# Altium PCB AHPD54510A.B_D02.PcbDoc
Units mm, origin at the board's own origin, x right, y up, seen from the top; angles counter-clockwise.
Board outline 70.4 x 70.4 mm, 2 copper layers (Top Layer, Bottom Layer), stack 1.57 mm thick; 18 components, 11 nets, 73 pads, 315 vias.
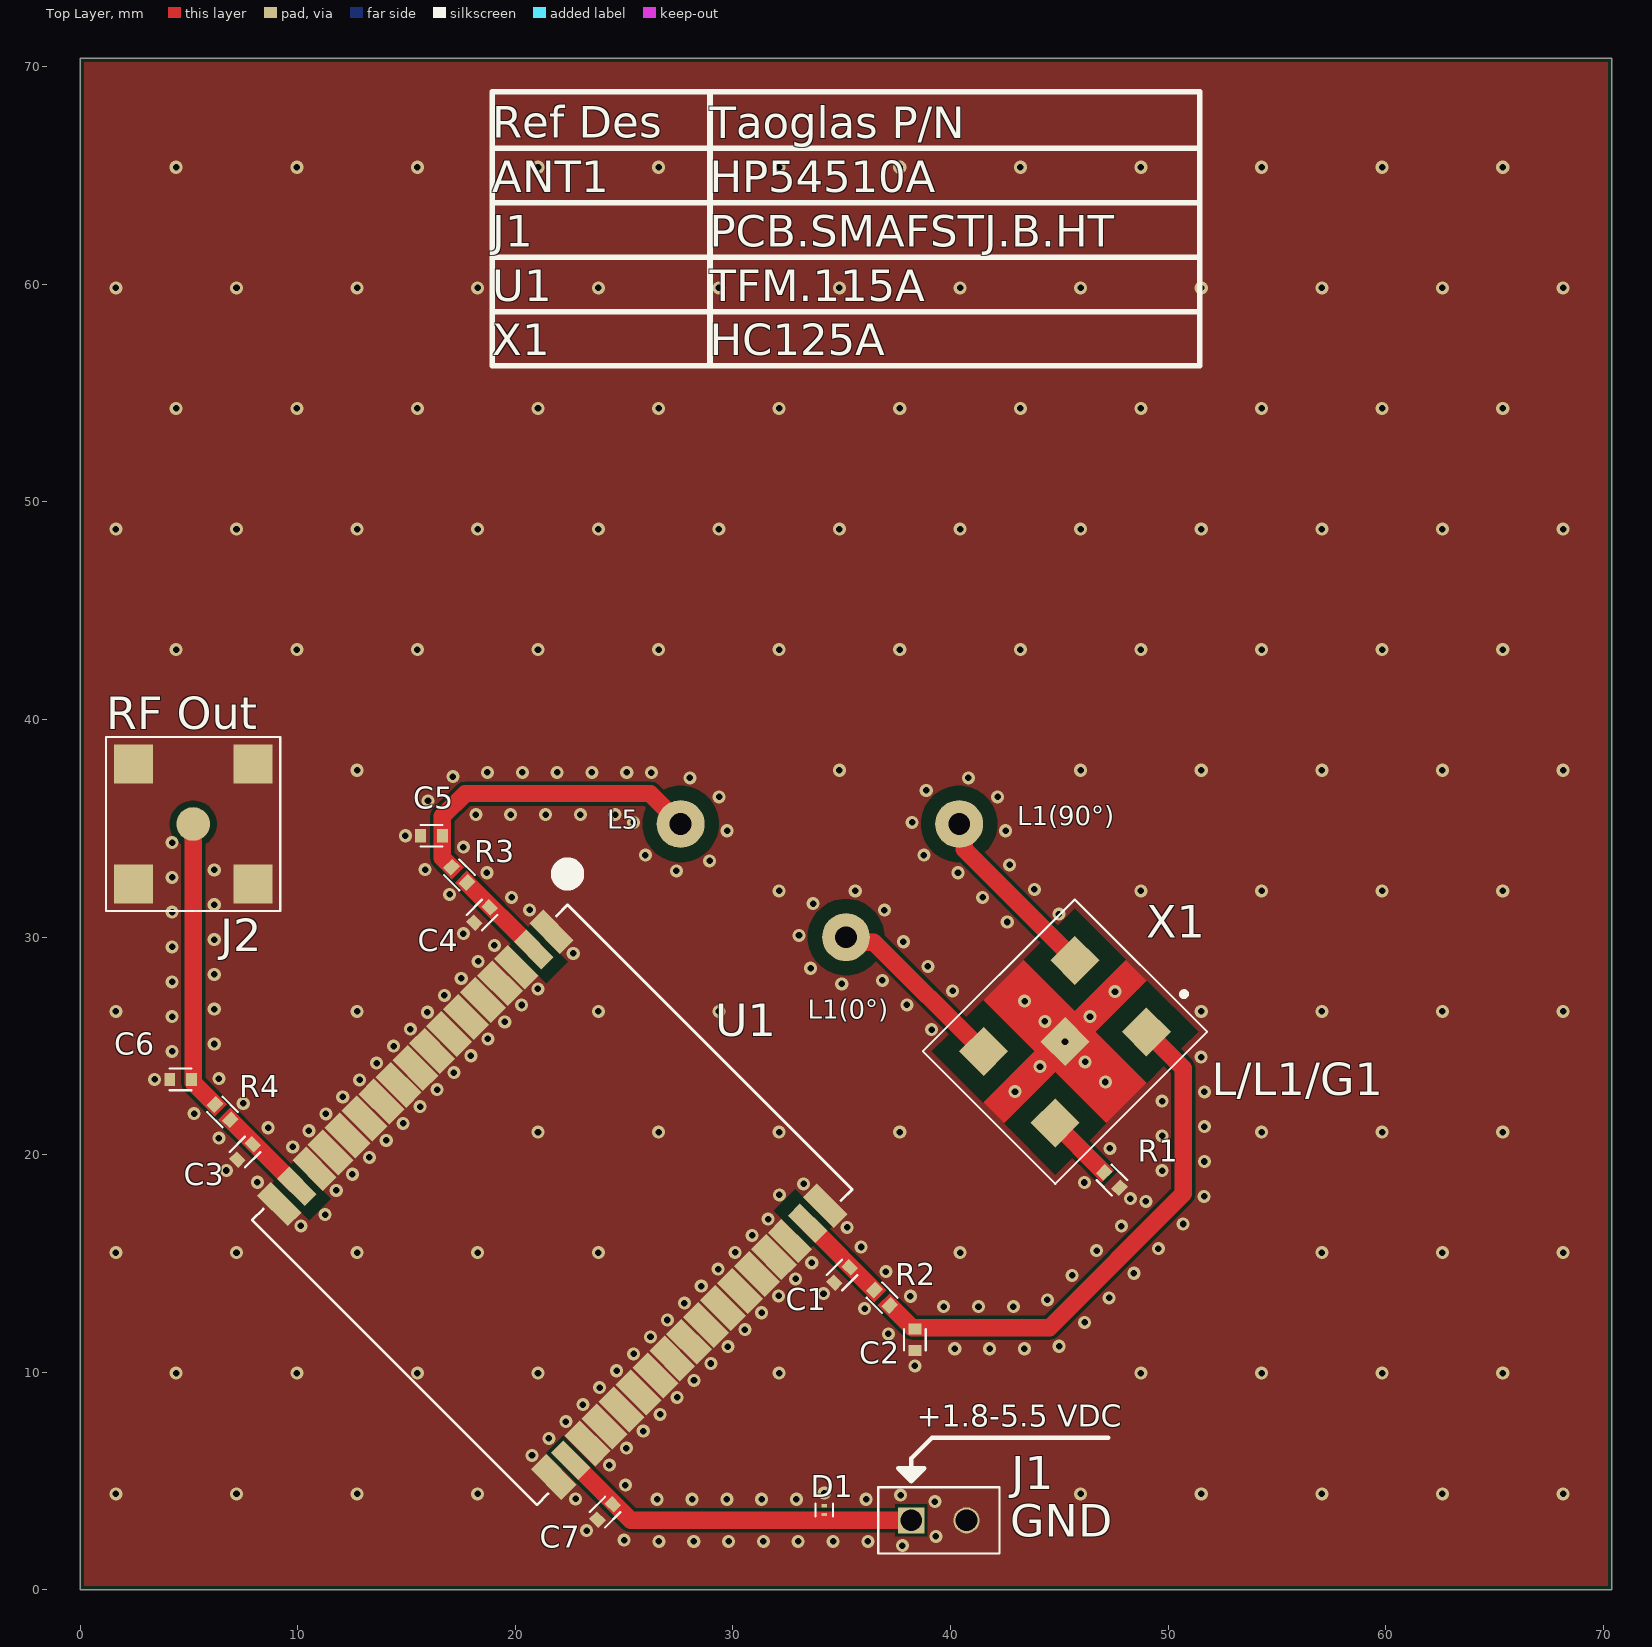
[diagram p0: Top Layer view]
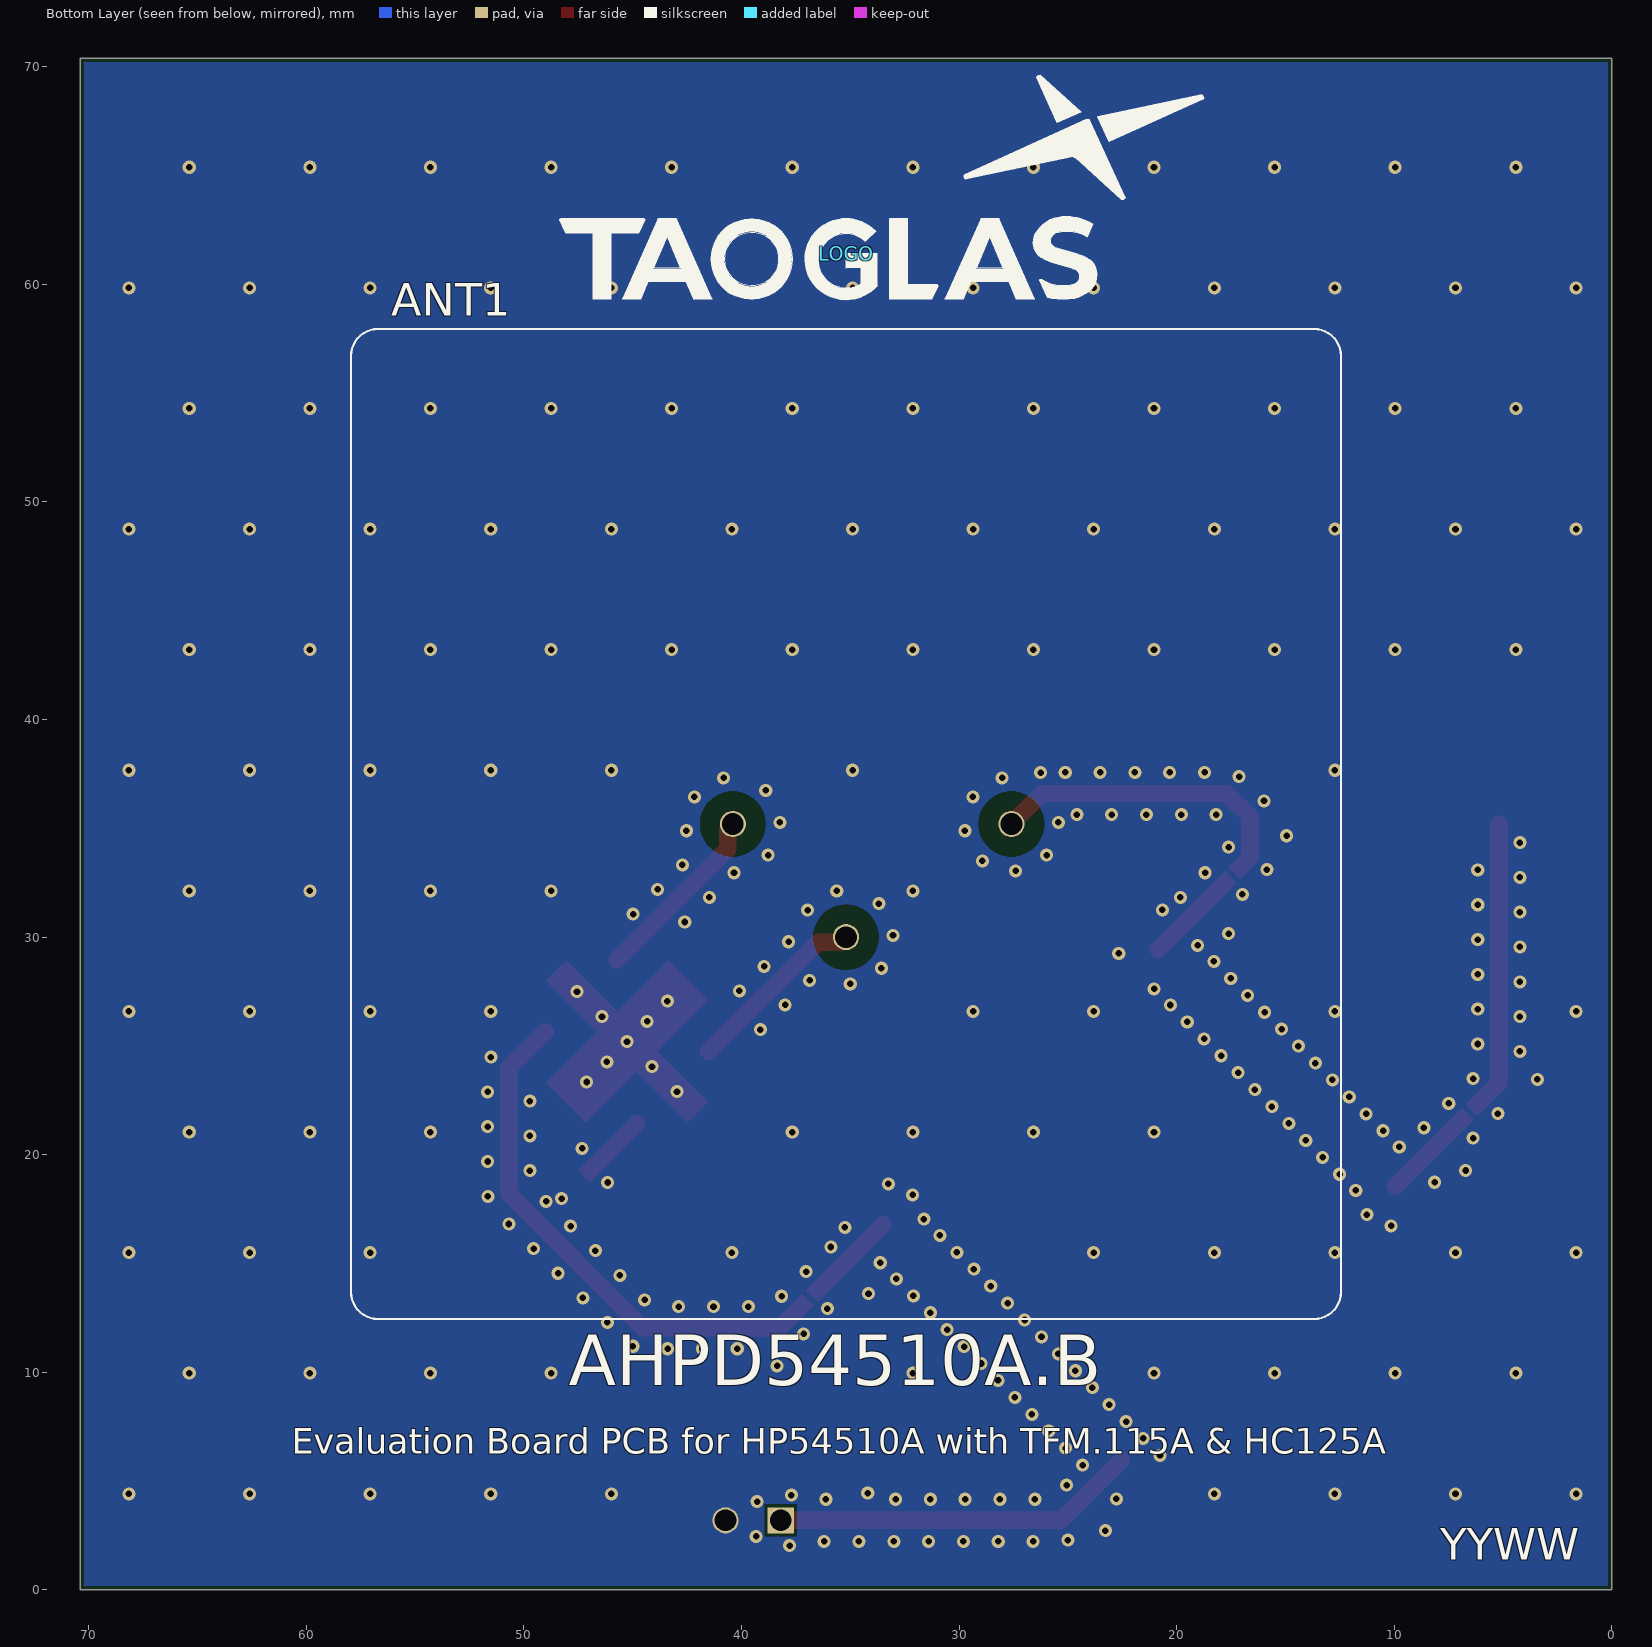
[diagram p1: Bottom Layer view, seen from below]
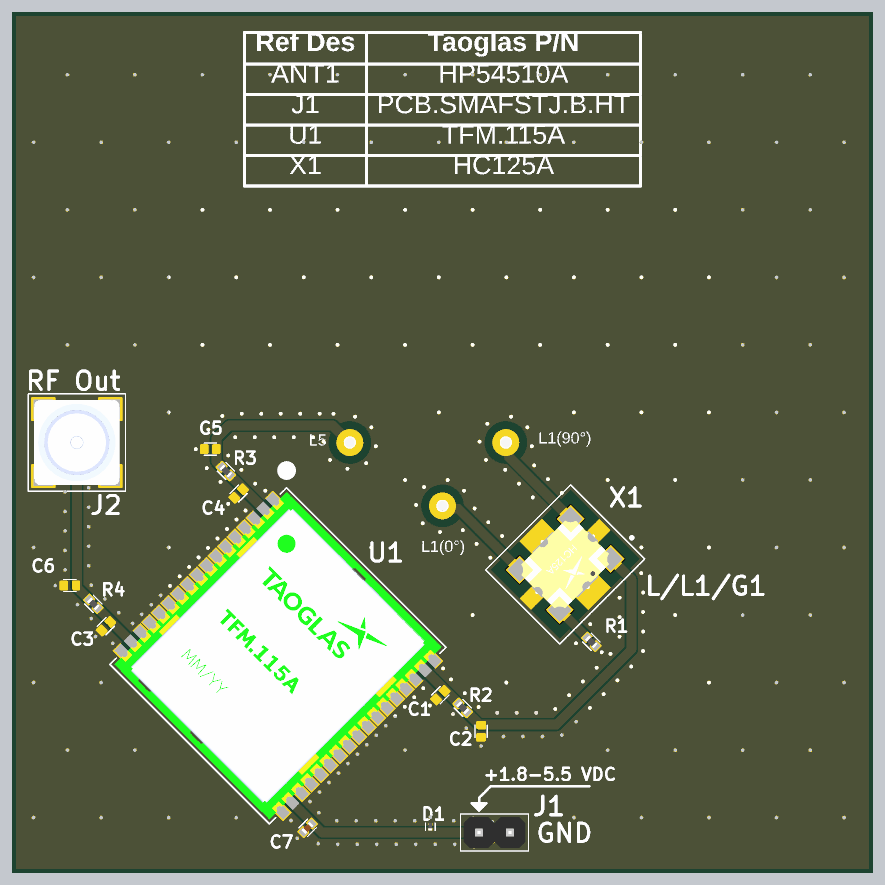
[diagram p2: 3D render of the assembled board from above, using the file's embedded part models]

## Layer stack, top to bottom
Top Solder Mask: solder mask 0.01, Solder Resist, Dk 3.5
Top Layer: signal copper 0.035
Dielectric: core 1.5, FR-4, Dk 4.2
Bottom Layer: signal copper 0.035
Bottom Solder Mask: solder mask 0.01, Solder Resist, Dk 3.5

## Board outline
0,0 70.4,0 70.4,70.4 0,70.4

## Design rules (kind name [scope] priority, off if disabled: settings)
BoardOutlineClearance [All] p1: gap=0.196 ignorepadtopadclearanceinfootprint=FALSE
Clearance Clearance_Polygon [All] p1: gap=0.14 ignorepadtopadclearanceinfootprint=FALSE except(0.05: Arc-Arc Arc-Track Track-Track; 0.1: Arc-SMDPad Arc-THPad Track-SMDPad Track-THPad SMDPad-SMDPad SMDPad-THPad THPad-THPad; 0.2: Arc-Via Arc-Text Arc-Hole Track-Via Track-Text Track-Hole SMDPad-Via SMDPad-Text SMDPad-Hole THPad-Via THPad-Text THPad-Hole Via-Via Via-Text Via-Hole Fill-Text Fill-Hole Poly-Text Poly-Hole Region-Text Region-Hole Text-Text Text-Hole)
HoleSize [All] p1: absolutevalues=TRUE maxlimit=6 minlimit=0.15 maxpercent=80.000 minpercent=20.000
MinimumAnnularRing [All] p1: minimumring=0.1
MinimumSolderMaskSliver [All vs InPadClass('All Pads')] p1: minsoldermaskwidth=0.05
PolygonConnect [All] p1: connectstyle=Direct reliefconductorwidth=0.254 reliefentries=4 polygonreliefangle="90 Angle" airgapwidth=0.254
RoutingVias [All] p1: holewidth=0.3 width=0.8 viastyle="Through Hole" minholewidth=0.15 minwidth=0.65 maxholewidth=6 maxwidth=6.5
SilkToSilkClearance [All] p1: silktosilkclearance=0.1
SilkToSolderMaskClearance [IsPad or IsVia vs OnLayer('Top Overlay')] p1: minsilkscreentomaskgap=0.05 clearancetoexposedcopper=FALSE
SilkToSolderMaskClearance SilkToSolderMaskClearance_1 [IsPad or IsVia vs OnLayer('Bottom Overlay')] p2: minsilkscreentomaskgap=0.05 clearancetoexposedcopper=FALSE
SolderMaskExpansion [Not IsVia] p1: expansion=0.1 istentingtop=FALSE
SupplyNets "Schematic Supply Nets" [InNet('GND')] p1: voltage=0.000
Width [All] p1: maxlimit=5 minlimit=0.1 preferedwidth=1 minimp=50.000000 maximp=50.000000 favimp=50.000000
26 further rules are at their usual default settings.

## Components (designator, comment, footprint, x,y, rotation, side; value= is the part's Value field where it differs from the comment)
ANT1 "TAOGLAS_HP54510A" TAOGLAS_HP54510A 35.2,35.2 r180 bottom
C1 "DNF" "0402 - DNF" 35.019,14.473 r225 top
C2 "DNF" "0402 - DNF" 38.368,11.499 r90 top
C3 "DNF" "0402 - DNF" 7.583,20.13 r45 top
C4 "DNF" "0402 - DNF" 18.473,31.019 r45 top
C5 "DNF" "0402 - DNF" 16.15,34.66 r180 top
C6 "DNF" "0402 - DNF" 4.623,23.467 r180 top
C7 "100pF" "Capacitor - 0402 - GRM" 24.13,3.583 r45 top
D1 "ESD245B1W0201E6327XTSA1" "Diode - 0201 (0603 Metric) - DSN0603-2" 34.2,3.67 r90 top
J1 "PREC002SAAN-RC" SULLINS_PREC002SAAN-RC 39.47,3.2 r0 top
J2 "TAOGLAS_PCB.SMAFSTJ.B.HT" TAOGLAS_PCB.SMAFSTJ.B.HT 5.2,35.2 r90 top
LOGO "TAOGLAS_LOGO" "TAOGLAS_LOGO - No R - 10.3mm" 35.2,61.4 r180 bottom
R1 "49.9" "Resistor - 0402 - ERJ-2RK" 47.415,18.837 r315 top
R2 "0" "Resistor - 0402 - RC_L" 36.861,13.428 r315 top
R3 "0" "Resistor - 0402 - RC_L" 17.428,32.861 r135 top
R4 "0" "Resistor - 0402 - RC_L" 6.552,21.959 r135 top
U1 "TAOGLAS_TFM.115A" TAOGLAS_TFM.115A 21.7,17.7 r315 top
X1 "TAOGLAS_HC125A" TAOGLAS_HC125A 45.264,25.2 r225 top

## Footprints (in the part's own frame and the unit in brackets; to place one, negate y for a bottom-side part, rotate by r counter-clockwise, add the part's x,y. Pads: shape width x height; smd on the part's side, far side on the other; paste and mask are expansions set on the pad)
"0402 - DNF" [mm]
  rect 0.5x0.6 smd paste-2539.97 mask+0.1: 1(-0.5,0) 2(0.5,0)
  silkscreen extent -0.5,-0.5 0.5,0.5
"Capacitor - 0402 - GRM" [mm]
  rect 0.5x0.6 smd mask+0.1: 1(-0.5,0) 2(0.5,0)
  silkscreen extent -0.5,-0.5 0.5,0.5, body extent -0.5,-0.25 0.5,0.25, height 0.55
"Diode - 0201 (0603 Metric) - DSN0603-2" [mm]
  rect 0.14x0.24 smd paste-2539.97 mask+0.05: 1(-0.2,0) 2(0.2,0)
  silkscreen extent -0.3,-0.4 0.3,0.4, body extent -0.3,-0.15 0.3,0.15, height 0.32
"Resistor - 0402 - ERJ-2RK" [mm]
  rect 0.5x0.6 smd mask+0.1: 1(-0.5,0) 2(0.5,0)
  silkscreen extent -0.5,-0.5 0.5,0.5, body extent -0.5,-0.25 0.5,0.25, height 0.35
"Resistor - 0402 - RC_L" [mm]
  rect 0.5x0.6 smd mask+0.1: 1(-0.5,0) 2(0.5,0)
  silkscreen extent -0.5,-0.5 0.5,0.5, body extent -0.5,-0.25 0.5,0.25, height 0.4
SULLINS_PREC002SAAN-RC [mm] "2 Positions Header, 0.100\" (2.54mm)"
  rect 1.2x1.2 hole 1 mask+0.1: 1(-1.27,0)
  round 1.2 hole 1 mask+0.1: 2(1.27,0)
  silkscreen extent -2.79,-1.52 2.79,2.12, body extent -2.54,-1.27 2.54,1.27, height 8.38
TAOGLAS_HC125A [mm] "Low Profile, High Performance Multiband GNSS Hybrid Coupler"
  rect 1.6x1.6 smd paste-0.1 mask+0.1: 1(-2.96,2.325) 2(2.96,2.325) 3(2.96,-2.325) 4(-2.96,-2.325)
  rect 1.6x1.6 smd: 5(0,0)
  Top Layer region: -4.62,0.665 -4.62,-0.665 -1.3,-0.665 -1.3,-3.985 1.3,-3.985 1.3,-0.665 4.62,-0.665 4.62,0.665 1.3,0.665 1.3,3.985 -1.3,3.985 -1.3,0.665
  silkscreen extent -5.51,-4.3 4.94,4.3, body extent -3.17,-2.54 3.18,2.54, height 1.5
TAOGLAS_HP54510A [mm] "Passive Multiband High Precision GNSS L1/L5 Stacked Patch Antenna"
  round 1.2 / inner round 2.2 / far side round 2.2 hole 1 paste-2539.97: 1(0,-5.2) 2(-5.2,0) 3(7.6,0)
  Bottom Layer pour cut-out: 7.6,-1.747 8.27,-1.614 8.837,-1.235 9.217,-0.667 9.35,0.003 9.35,0.003 9.35,0.003 9.217,0.672 8.837,1.24 8.27,1.619 7.6,1.753 7.6,1.753 6.93,1.619 6.363,1.24 5.983,0.672 5.85,0.003 5.85,0.003 5.85,0.003 5.983,-0.667 6.363,-1.235 6.93,-1.614 7.6,-1.747
  Bottom Layer pour cut-out: -5.2,-1.747 -4.53,-1.614 -3.963,-1.235 -3.583,-0.667 -3.45,0.003 -3.45,0.003 -3.45,0.003 -3.583,0.672 -3.963,1.24 -4.53,1.619 -5.2,1.753 -5.2,1.753 -5.87,1.619 -6.437,1.24 -6.817,0.672 -6.95,0.003 -6.95,0.003 -6.95,0.003 -6.817,-0.667 -6.437,-1.235 -5.87,-1.614 -5.2,-1.747
  Bottom Layer pour cut-out: 0,-6.947 0.67,-6.814 1.237,-6.435 1.617,-5.867 1.75,-5.197 1.75,-5.197 1.75,-5.197 1.617,-4.528 1.237,-3.96 0.67,-3.581 0,-3.447 0,-3.447 -0.67,-3.581 -1.237,-3.96 -1.617,-4.528 -1.75,-5.197 -1.75,-5.197 -1.75,-5.197 -1.617,-5.867 -1.237,-6.435 -0.67,-6.814 0,-6.947
  Multi-Layer pour cut-out: 6.1,0 6.214,-0.574 6.539,-1.061 7.026,-1.386 7.6,-1.5 7.6,-1.5 8.174,-1.386 8.661,-1.061 8.986,-0.574 9.1,0 9.1,0 8.986,0.574 8.661,1.061 8.174,1.386 7.6,1.5 7.6,1.5 7.026,1.386 6.539,1.061 6.214,0.574 6.1,0
  Multi-Layer pour cut-out: -6.7,0 -6.586,-0.574 -6.261,-1.061 -5.774,-1.386 -5.2,-1.5 -5.2,-1.5 -4.626,-1.386 -4.139,-1.061 -3.814,-0.574 -3.7,0 -3.7,0 -3.814,0.574 -4.139,1.061 -4.626,1.386 -5.2,1.5 -5.2,1.5 -5.774,1.386 -6.261,1.061 -6.586,0.574 -6.7,0
  Multi-Layer pour cut-out: -1.5,-5.2 -1.386,-5.774 -1.061,-6.261 -0.574,-6.586 0,-6.7 0,-6.7 0.574,-6.586 1.061,-6.261 1.386,-5.774 1.5,-5.2 1.5,-5.2 1.386,-4.626 1.061,-4.139 0.574,-3.814 0,-3.7 0,-3.7 -0.574,-3.814 -1.061,-4.139 -1.386,-4.626 -1.5,-5.2
  silkscreen extent -22.75,-22.75 22.75,22.75, body extent -22.5,-22.5 22.5,22.5, height 10.2
"TAOGLAS_LOGO - No R - 10.3mm" [mm] "Total Height from bottom of the text to the top of the star is 10.3mm"
  silkscreen extent -13.15,-2.12 16.43,8.2
TAOGLAS_PCB.SMAFSTJ.B.HT [mm] "SMA (F) Surface Mount PCB Jack"
  round 1.55 smd paste-0.1 mask+0.1: 1(0,0)
  rect 1.8x1.8 smd paste-0.1 mask+0.1: 2(-2.75,2.75) 3(2.75,2.75) 4(-2.75,-2.75) 5(2.75,-2.75)
  silkscreen extent -4,-4 4,4, body extent -3.5,-3.5 3.5,3.5, height 10.23
TAOGLAS_TFM.115A [mm] "GNSS Front End Module for Bands L1, B1, G1, L Band and L5"
  rect 2x0.9 smd paste-2539.97 mask+0: 1(-8.9,8.85) 3(-8.9,6.55) 15(-8.9,-6.55) 17(-8.9,-8.85) 32(8.9,6.55) 34(8.9,8.85)
  rect 1.8x0.8 smd paste-2539.97: 2(-8.9,7.7) 16(-8.9,-7.7) 19(8.9,-7.7) 33(8.9,7.7)
  rect 2x1 smd paste-2539.97 mask+0: 4(-8.9,5.5) 5(-8.9,4.4) 6(-8.9,3.3) 7(-8.9,2.2) 8(-8.9,1.1) 9(-8.9,0) 10(-8.9,-1.1) 11(-8.9,-2.2) 12(-8.9,-3.3) 13(-8.9,-4.4) 14(-8.9,-5.5) 18(8.9,-8.8) 20(8.9,-6.6) 21(8.9,-5.5) 22(8.9,-4.4) 23(8.9,-3.3) 24(8.9,-2.2) 25(8.9,-1.1) 26(8.9,0) 27(8.9,1.1) 28(8.9,2.2) 29(8.9,3.3) 30(8.9,4.4) 31(8.9,5.5)
  silkscreen extent -10.5,-10.25 9.25,11.5, body extent -9,-10 9,10, height 2.74

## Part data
ANT1: library part CMP-270-000002-3, "Passive Multiband High Precision GNSS L1/L5 Stacked Patch Antenna", Temp_High=+85C, Temp_Low=-40C
C1 C2 C3 C4 C5 C6: library part CMP-00006-25, "Do Not Fit"
C7: library part CMP-001-00343-45, "100 pF ±5% 50V Ceramic Capacitor C0G, NP0 0402 (1005 Metric)", Max. Operating Temperature=125°C, Min. Operating Temperature=-55°C, Package / Case="0402 (1005 Metric)", Temperature Coefficient="C0G, NP0", Tolerance=±5%, Voltage - Rated=50V
D1: library part CMP-004-00167-10, "7.5V Clamp 5.5A (8/20µs) Ipp Tvs Diode Surface Mount WLL-2-3", Capacitance @ Frequency="5.8pF @ 1GHz", Current - Peak Pulse (10/1000µs)="5.5A (8/20µs)", Max. Operating Temperature=125°C, Max. Voltage - Clamping @ Ipp=7.5V, Min. Operating Temperature=-55°C, Package / Case="0201 (0603 Metric)", Power - Peak Pulse=44W, Power Line Protection=No, Supplier Device Package=WLL-2-3, Voltage - Reverse Standoff (Typ)=5.5V
J1: library part CMP-002-00180-7, "Connector Header Through Hole 2 position 0.100\" (2.54mm)", Temp_High=105°C, Temp_Low=-40°C
J2: library part CMP-028-000009-10, "SMA (F) Surface Mount PCB Jack", Temp_High=+85C, Temp_Low=-40C
LOGO: library part CMP-048-000000-2, "Silkscreen Logo - Standard"
R1: library part CMP-009-00256-10, "49.9 Ohms ±1% 0.1W, 1/10W Chip Resistor 0402 (1005 Metric) Automotive AEC-Q200 Thick Film", Max. Operating Temperature=155°C, Min. Operating Temperature=-25°C, Package / Case="0402 (1005 Metric)", Power (Watts)=100mW, Temperature Coefficient=±100ppm/°C, Tolerance=±1%
R2 R3 R4: library part CMP-009-00375-4, "0 Ohms Jumper Chip Resistor 0402 (1005 Metric) Moisture Resistant Thick Film", Max. Operating Temperature=155°C, Min. Operating Temperature=-55°C, Package / Case="0402 (1005 Metric)"
U1: library part CMP-559-000000-3, "Surface mount GNSS front-end module covering L1+B1+G1/L5+L-band", Temp_High=+85C, Temp_Low=-40C
X1: library part CMP-002-000151-19, "Low Profile, High Performance Multiband GNSS Hybrid Coupler", Center Frequency=1.39GHz

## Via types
v1: diameter 0.6, hole 0.3, Top Layer to Bottom Layer, tented both sides, 315 vias

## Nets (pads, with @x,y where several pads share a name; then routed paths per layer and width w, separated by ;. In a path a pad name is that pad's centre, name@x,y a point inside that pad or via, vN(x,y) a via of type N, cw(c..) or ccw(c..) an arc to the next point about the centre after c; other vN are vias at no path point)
GND: C1.2 C2.1 C3.1 C4.1 C5.2 C6.2 C7.1 D1.2 J1.2 J2.2 J2.3 J2.4 J2.5 R1.2 U1.1 U1.3 U1.4 U1.5 U1.6 U1.7 U1.8 U1.9 U1.10 U1.11 U1.12 U1.13 U1.14 U1.15 U1.17 U1.18 U1.20 U1.21 U1.22 U1.23 U1.24 U1.25 U1.26 U1.27 U1.28 U1.29 U1.30 U1.31 U1.32 U1.34 X1.5
  other v1: 37.792,2.039 26.603,2.231 28.203,2.231 29.803,2.231 31.403,2.231 33.003,2.231 34.603,2.231 36.203,2.231 25.004,2.29 39.334,2.465 23.276,2.73 39.285,4.065 22.771,4.184 26.524,4.169 28.124,4.169 29.724,4.169 31.324,4.169 32.924,4.169 36.124,4.169 37.712,4.361 1.648,4.419 7.19,4.419 12.732,4.419 18.274,4.419 45.984,4.419 51.526,4.419 57.068,4.419 62.61,4.419 68.152,4.419 34.2,4.455 25.062,4.819 24.326,5.74 20.771,6.184 25.104,6.518 21.549,6.962 25.882,7.295 22.326,7.74 26.66,8.073 23.104,8.518 27.438,8.851 23.882,9.295 28.215,9.629 4.419,9.961 9.961,9.961 15.503,9.961 21.045,9.961 32.129,9.961 48.755,9.961 54.297,9.961 59.839,9.961 65.381,9.961 24.66,10.073 38.368,10.299 28.993,10.407 25.438,10.851 40.198,11.084 41.798,11.084 43.398,11.084 29.771,11.185 44.994,11.199 26.215,11.629 37.152,11.768 30.549,11.962 46.162,12.292 26.993,12.407 31.327,12.74 36.055,12.933 39.689,13.021 41.289,13.021 42.889,13.021 27.771,13.185 44.459,13.329 47.294,13.424 38.162,13.498 32.105,13.518 34.166,13.619 28.549,13.962 32.882,14.296 45.59,14.46 48.425,14.555 37.03,14.629 29.327,14.74 33.625,15.038 1.648,15.503 7.19,15.503 12.732,15.503 18.274,15.503 23.816,15.503 30.105,15.518 40.442,15.503 57.068,15.503 62.61,15.503 68.152,15.503 46.722,15.592 49.556,15.686 35.899,15.76 30.882,16.296 35.251,16.665 10.149,16.735 47.853,16.723 50.688,16.818 31.625,17.038 11.262,17.249 48.985,17.854 48.269,17.984 51.658,18.09 32.138,18.151 11.775,18.362 33.251,18.665 8.149,18.735 46.158,18.725 12.518,19.104 6.73,19.276 49.731,19.269 51.669,19.69 13.295,19.882 47.329,20.294 9.775,20.362 14.073,20.66 6.378,20.763 49.731,20.869 21.045,21.045 26.587,21.045 32.129,21.045 37.671,21.045 54.297,21.045 59.839,21.045 65.381,21.045 10.518,21.104 8.64,21.241 51.669,21.29 14.851,21.438 5.246,21.894 11.295,21.882 15.629,22.215 7.5,22.363 49.731,22.469 12.073,22.66 42.966,22.902 51.669,22.89 16.407,22.993 47.121,23.344 12.851,23.438 3.423,23.467 6.377,23.503 17.185,23.771 44.115,24.051 13.629,24.215 46.192,24.272 51.516,24.483 17.962,24.549 4.231,24.748 14.407,24.993 6.169,25.09 45.264,25.2 18.74,25.327 39.131,25.752 15.185,25.771 19.518,26.105 44.336,26.128 4.231,26.348 46.413,26.349 15.962,26.549 1.648,26.587 12.732,26.587 23.816,26.587 29.358,26.587 51.526,26.587 57.068,26.587 62.61,26.587 68.152,26.587 6.169,26.69 20.296,26.882 38,26.883 43.408,27.056 16.74,27.327 47.562,27.498 40.095,27.527 21.038,27.625 35.004,27.848 4.231,27.948 36.869,28.014 17.518,28.105 6.169,28.29 33.576,28.57 38.964,28.659 18.296,28.882 22.665,29.251 4.231,29.548 19.038,29.625 37.833,29.79 6.169,29.89 33.041,30.078 17.619,30.166 42.61,30.696 44.986,31.06 4.231,31.148 20.665,31.251 36.965,31.247 6.169,31.49 33.687,31.541 19.832,31.828 41.479,31.827 16.986,31.969 32.129,32.129 35.625,32.122 48.755,32.129 54.297,32.129 59.839,32.129 65.381,32.129 43.855,32.191 4.231,32.748 18.7,32.959 40.347,32.959 27.404,33.048 6.169,33.09 15.855,33.1 42.723,33.322 28.937,33.505 25.976,33.77 38.776,33.77 17.619,34.138 4.231,34.348 14.95,34.66 29.737,34.89 42.537,34.89 25.441,35.278 38.241,35.278 18.192,35.631 19.792,35.631 21.392,35.631 22.992,35.631 24.592,35.631 15.991,36.261 29.365,36.447 42.165,36.447 38.887,36.741 28.025,37.322 40.825,37.322 17.135,37.378 18.724,37.569 20.324,37.569 21.924,37.569 23.524,37.569 25.124,37.569 26.254,37.558 12.732,37.671 34.9,37.671 45.984,37.671 51.526,37.671 57.068,37.671 62.61,37.671 68.152,37.671 4.419,43.213 9.961,43.213 15.503,43.213 21.045,43.213 26.587,43.213 32.129,43.213 37.671,43.213 43.213,43.213 48.755,43.213 54.297,43.213 59.839,43.213 65.381,43.213 1.648,48.755 7.19,48.755 12.732,48.755 18.274,48.755 23.816,48.755 29.358,48.755 34.9,48.755 40.442,48.755 45.984,48.755 51.526,48.755 57.068,48.755 62.61,48.755 68.152,48.755 4.419,54.297 9.961,54.297 15.503,54.297 21.045,54.297 26.587,54.297 32.129,54.297 37.671,54.297 43.213,54.297 48.755,54.297 54.297,54.297 59.839,54.297 65.381,54.297 1.648,59.839 7.19,59.839 12.732,59.839 18.274,59.839 23.816,59.839 29.358,59.839 34.9,59.839 40.442,59.839 45.984,59.839 51.526,59.839 57.068,59.839 62.61,59.839 68.152,59.839 4.419,65.381 9.961,65.381 15.503,65.381 21.045,65.381 26.587,65.381 32.129,65.381 37.671,65.381 43.213,65.381 48.755,65.381 54.297,65.381 59.839,65.381 65.381,65.381
NetANT1_1: ANT1.1 X1.3 | length 8.5
  Top Layer w0.8: ANT1.1 35.43,29.77 36.482,29.77 X1.3@41.502,24.751
NetANT1_2: ANT1.2 X1.4 | length 8.4
  Top Layer w0.8: ANT1.2 40.63,34.97 40.63,34.046 X1.4@45.713,28.963
NetANT1_3: ANT1.3 C5.1 R3.2 | length 14.6
  Top Layer w0.8: R3.2 16.65,33.639 16.65,34.731 C5.1 16.65,35.55 17.7,36.6 26.2,36.6 ANT1.3
NetC1_1: C1.1 R2.1 U1.33 | length 4.2
  Top Layer w0.8: U1.33@33.509,16.781 R2.1
NetC2_2: C2.2 R2.2 X1.1 | length 24.6
  Top Layer w0.8: R2.2 38.237,12.053 38.368,12.053 44.553,12.053 50.7,18.2 50.7,23.975 X1.1@49.026,25.649
NetC3_2: C3.2 R4.1 U1.16 | length 4.3
  Top Layer w0.8: R4.1 U1.16
NetC4_2: C4.2 R3.1 U1.2 | length 4.3
  Top Layer w0.8: R3.1 U1.2
NetC6_1: C6.1 J2.1 R4.2 | length 13.3
  Top Layer w0.8: J2.1 5.2,23.311 R4.2
NetC7_2: C7.2 D1.1 J1.1 U1.19 | length 16.8
  Top Layer w0.8: U1.19 25.311,3.2 30.2,3.2 J1.1
NetR1_1: R1.1 X1.2 | length 3
  Top Layer w0.8: X1.2@44.815,21.438 R1.1@46.962,19.291

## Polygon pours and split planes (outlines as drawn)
GND on Bottom Layer "GND_L02_P000" (solid, remove dead copper, pour order 1): 0,0 70.4,0 70.4,70.4 0,70.4
GND on Top Layer "GND_L01_P000" (solid, remove dead copper, pour order 0): 0,0 70.4,0 70.4,70.4 0,70.4

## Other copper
Top Layer:
  region net NetR1_1: 46.962,18.725 47.527,19.291 46.962,19.857 46.396,19.291
  region net NetANT1_3: 17.075,32.649 17.64,33.215 17.075,33.781 16.509,33.215
  region net NetC4_2: 17.782,31.942 18.347,32.508 17.782,33.074 17.216,32.508
  region net NetC3_2: 6.906,21.039 7.471,21.605 6.906,22.171 6.34,21.605
  region net NetC6_1: 6.198,21.746 6.764,22.312 6.198,22.878 5.633,22.312
  region net NetC1_1: 36.508,13.216 37.074,13.782 36.508,14.347 35.942,13.782
  region net NetC2_2: 37.215,12.509 37.781,13.075 37.215,13.64 36.649,13.075
  pour cut-out: 4.125,35.2 ccw(c5.2,35.2) 5.2,34.125 ccw(c5.2,35.2) 6.275,35.2 ccw(c5.2,35.2) 5.2,36.275 ccw(c5.2,35.2) 4.125,35.2
  pour cut-out: 6.091,21.639 6.871,22.419 7.013,22.278 6.233,21.498
  pour cut-out: 16.967,32.542 17.747,33.322 17.889,33.181 17.109,32.401
  pour cut-out: 36.401,13.109 37.181,13.889 37.322,13.747 36.542,12.967
  pour cut-out: 46.855,18.618 47.635,19.398 47.742,19.291 46.962,18.511
  pour cut-out: 21.424,6.308 22.202,7.087 22.938,6.351 22.159,5.573
  pour cut-out: 31.882,17.417 32.872,18.407 34.569,16.71 33.579,15.72
  pour cut-out: 8.831,18.69 9.821,19.68 11.518,17.983 10.528,16.993
  pour cut-out: 19.72,29.579 20.71,30.569 22.407,28.872 21.417,27.882
  pour cut-out: 44.815,23.789 47.167,21.438 44.815,19.086 42.464,21.438
  pour cut-out: 41.502,27.102 43.854,24.751 41.502,22.399 39.15,24.751
  pour cut-out: 45.714,31.314 48.065,28.963 45.713,26.611 43.362,28.962
  pour cut-out: 49.027,28.001 51.378,25.649 49.027,23.298 46.675,25.649
  text ".Layer_Name" at -44.35,55.034 h2
Bottom Layer:
  text ".Layer_Name" at -44.35,50.034 h2

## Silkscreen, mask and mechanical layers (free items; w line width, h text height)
Top Overlay:
  rectangle: 37.793,5.331 38.604,5.659
  rectangle: 37.965,5.155 38.418,5.439
  region: 195.173,23.762 195.173,24.215
  lines w0.2: 38.2,5.086 38.2,6.048 39.149,6.997 47.251,6.997 ; 37.603,5.597 38.2,5 38.797,5.597 37.603,5.597
  lines w0.254: 18.95,58.75 51.45,58.75 ; 18.95,61.25 51.45,61.25 ; 18.95,63.75 51.45,63.75 ; 18.95,66.25 51.45,66.25 ; 28.95,56.25 28.95,68.85 ; 18.95,56.25 18.95,68.85 51.45,68.85 51.45,56.25 18.95,56.25
  text "Ref Des" at 18.95,66.25 h2.5
  text "Taoglas P/N" at 28.95,66.229 h2.5
  text "ANT1" at 18.95,63.75 h2.5
  text "HP54510A" at 28.95,63.75 h2.5
  text "J1" at 18.95,61.25 h2.5
  text "PCB.SMAFSTJ.B.HT" at 28.95,61.25 h2.5
  text "U1" at 18.95,58.75 h2.5
  text "TFM.115A" at 28.95,58.75 h2.5
  text "X1" at 18.95,56.25 h2.5
  text "HC125A" at 28.95,56.25 h2.5
  text ".Layer_Name" at -44.35,45.034 h2
  text "RF Out" at 1.201,39.55 h1.5
  text "L1(90°)" at 43.066,34.853 h1.5
  text "L5" at 24.23,34.678 h1.5
  text "L1(0°)" at 33.439,25.953 h1.5
  text "L/L1/G1" at 51.998,22.724 h1.5
  text "+1.8-5.5 VDC" at 38.45,7.5 h1
  text "GND" at 42.75,2.45 h1.5
Bottom Overlay:
  text ".Layer_Name" at -44.35,40.034 h2
  text "AHPD54510A.B" at 47.949,8.635 h4
  text "Evaluation Board PCB for HP54510A with TFM.115A & HC125A" at 60.667,5.862 h2
  text "YYWW" at 7.898,0.9 h2.5
Top Paste:
  text ".Layer_Name" at -44.35,25.034 h2
Bottom Paste:
  text ".Layer_Name" at -44.35,19.7 h2
Top Solder Mask:
  text ".Layer_Name" at -44.35,35.034 h2
Bottom Solder Mask:
  text ".Layer_Name" at -44.35,29.7 h2
Board Outline:
  the board outline again, w0.254
  text ".Layer_Name" at -44.35,59.7 h2
Top Assembly:
  text ".Layer_Name" at -44.35,15.034 h2
Bottom Assembly:
  text ".Layer_Name" at -44.35,10.034 h2
IDW (Mech7):
  drawing of 191 lines, arcs and shapes, not listed
  text "Layer" at -24.627,-12.546 h1.52
  text "Name" at -14.216,-12.546 h1.52
  text "Material" at 15.24,-12.546 h1.52
  text "Thickness" at 37.078,-12.546 h1.52
  text "Constant" at 53.584,-12.546 h1.52
  text "Board Layer Stack" at 68.058,-12.546 h1.52
  text "Top Overlay" at -14.216,-15.594 h1.52
  text "Top Solder Mask" at -14.216,-18.642 h1.52
  text "Solder Resist" at 15.24,-18.642 h1.52
  text "0.010mm" at 37.078,-18.642 h1.52
  text "3.5" at 53.584,-18.642 h1.52
  text "1" at -24.627,-21.69 h1.52
  text "Top Layer" at -14.216,-21.69 h1.52
  text "0.035mm" at 37.078,-21.69 h1.52
  text "Dielectric" at -14.216,-24.738 h1.52
  text "FR-4" at 15.24,-24.738 h1.52
  text "1.500mm" at 37.078,-24.738 h1.52
  text "4.2" at 53.584,-24.738 h1.52
  text "2" at -24.627,-27.786 h1.52
  text "Bottom Layer" at -14.216,-27.786 h1.52
  text "0.035mm" at 37.078,-27.786 h1.52
  text "Bottom Solder Mask" at -14.216,-30.834 h1.52
  text "Solder Resist" at 15.24,-30.834 h1.52
  text "0.010mm" at 37.078,-30.834 h1.52
  text "3.5" at 53.584,-30.834 h1.52
  text "Bottom Overlay" at -14.216,-33.882 h1.52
